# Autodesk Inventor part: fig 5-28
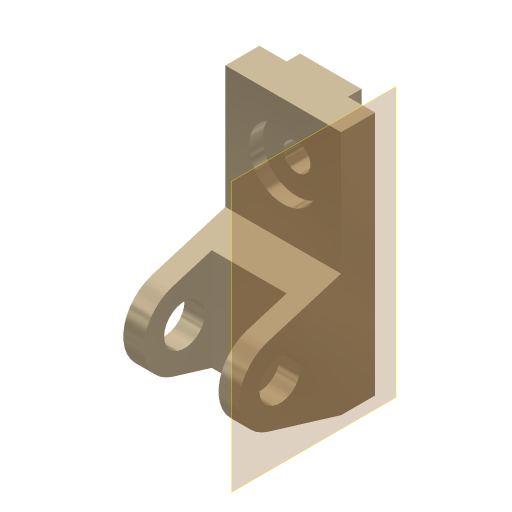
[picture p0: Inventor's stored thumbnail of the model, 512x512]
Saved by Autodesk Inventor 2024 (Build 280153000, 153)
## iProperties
Shininess: 65.0
Angle Display Precision: 2
Document Length Units: 11269
Document Angle Units: 11279
Document Time Units: 11290
Document Mass Units: 11283
Document Length Units Precision: 3
Document Angle Units Precision: 2
Created: 2001-11
Part Number: fig 5-28
Document SubType Name: Modeling
Designer: Renu Muthoo
Density: 1 g/cm^3
Material: Generic
Appearance: Metal-Titanium (Polished)
Density: 0.0
Volumn: 0.0
Area: 0.0
PropertySet Name: Model Information
Control State: 0
Master: False
Checked Out: False
Author: Renu Muthoo
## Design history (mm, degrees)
sketch "Sketch2"
  geometry: L1 (33.257, 104.664)-(33.257, -75.336); L2 (33.257, -75.336)-(8.257, -75.336); L3 (8.257, -75.336)-(-45.451, -59.045); L4 (-45.451, -1.628)-(8.257, 14.664); L5 (8.257, 14.664)-(8.257, 104.664); L6 (8.257, 104.664)-(33.257, 104.664); C1 r 15 at (-36.743, -30.336); A1 r 30 centre (-36.743, -30.336) between (-45.451, -1.628) and (-45.451, -59.045)
  constraints: 12 end point, 2 centre point, 2 equal length, 2 parallel, 2 point on circle, 2 tangent, 1 coincident, 1 perpendicular, 1 vertical
  dimensions: "d0" = 180 distance of L1.start L1.end; "d1" = 30 radius of A1; "d2" = 25 distance of L5.end L1.start; "d3" = 45 distance from line of L2 A1.centre; "d4" = 70 distance from line of L1 A1.centre; "d5" = 30 diameter of C1
extrude "Extrusion1" new body sketch "Sketch2" distance "d6" = 85; taper "d7" = 0 deg
workplane "Work Plane1"
sketch "Sketch3"
  geometry: L1 (15, 62.364)-(70, 62.364); L2 (70, 62.364)-(70, -52.386); L3 (70, -52.386)-(15, -52.386); L4 (15, -52.386)-(15, 62.364); L5 (0, -45)-(0, -28.708) reference
  constraints: 8 end point, 2 parallel, 1 horizontal, 1 perpendicular
  dimensions: "d8" = 55 distance of L1.start L1.end; "d9" = 15 distance between parallel lines of L5 L4
extrude "Extrusion2" cut sketch "Sketch3" distance "d10" = 50; taper "d11" = 0 deg
sketch "Sketch4"
  geometry: L1 (0, 25)-(85, 25) reference; L2 (0, 0)-(0, 25) reference; L3 (20, 25)-(65, 25); L4 (65, 25)-(65, 35); L5 (65, 35)-(20, 35); L6 (20, 35)-(20, 25)
  constraints: 8 end point, 2 parallel, 1 horizontal, 1 perpendicular, 1 point on line
  dimensions: "d12" = 45 distance of L4.end L5.end; "d13" = 10 distance of L3.end L4.end; "d14" = 20 distance between parallel lines of L2 L6
extrude "Extrusion3" join sketch "Sketch4" stored distance "d15" = 50; taper "d16" = 0 deg
sketch "Sketch5"
  geometry: L1 (85, 0)-(85, 90) reference; L2 (0, 90)-(85, 90) reference; 1 further point
  dimensions: "d17" = 42 distance from line of L2 point (42.5, 48); "d18" = 42.5 distance from line of L1 point (42.5, 48)
hole "Hole1" sketch "Sketch5" diameter "d19" = 20; stored, may be unused: countersink angle "d23" = 82 deg, drill point angle "d25" = 118 deg; dims "d20" = 6, "d21" = 50, "d22" = 10, "d24" = 8
workplane "Work Plane4"
body "Solid1"
node "Sketch1"
other parameters: "d26" = 0
